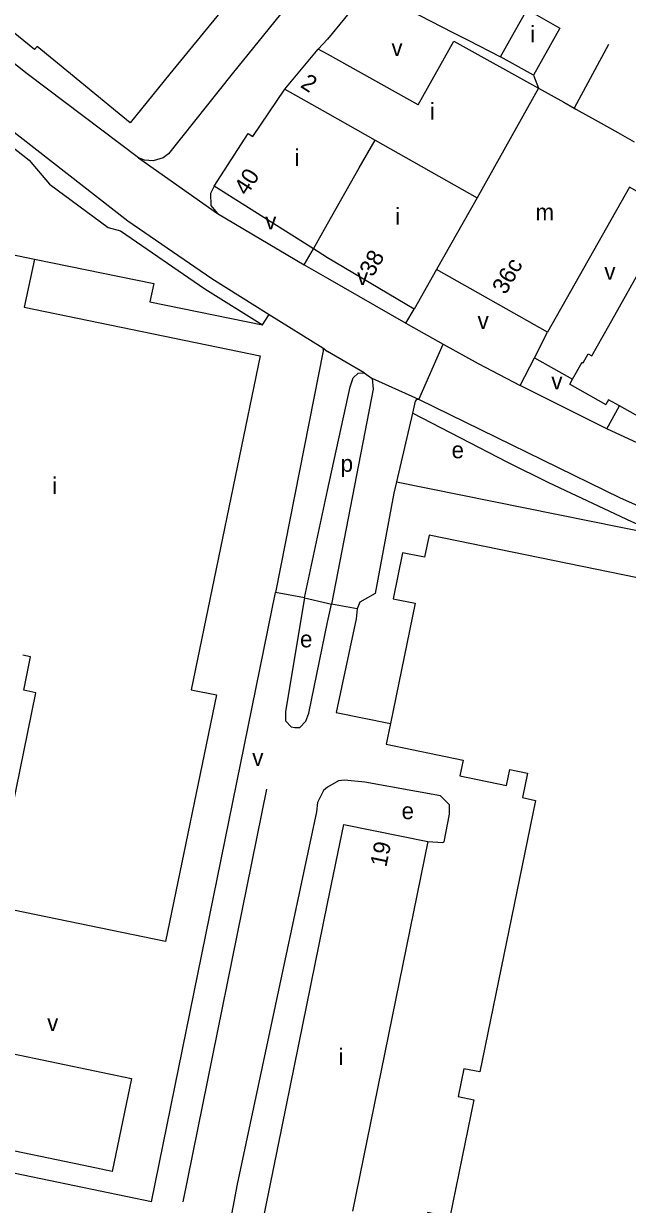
# Model space of a CAD drawing. Extents: x 157699 to 159683, y 381451 to 383293.
# Drawn here: x 157977.1 to 158121.9, y 382628.7 to 382912.1 of the extents above; entities that cross this region are included whole.
import ezdxf

# ---------------------------------------------------------------- set-up
doc = ezdxf.new("R2010")
doc.units = 0
for name, color, linetype in [('BLT_Basislijn', 7, 'Continuous'), ('BLT_Bebouwing', 7, 'Continuous'), ('BLT_Centroide', 7, 'Continuous'), ('BLT_Huisnummer', 7, 'Continuous'), ('BLT_Onderverdeling_panden', 7, 'Continuous'), ('BLT_Vlakafsluiter', 7, 'Continuous')]:
    doc.layers.add(name, color=color, linetype=linetype)

msp = doc.modelspace()

# ---------------------------------------------------------------- linework, layer by layer
at = {"layer": 'BLT_Basislijn'}
for p, q in [((158059.8, 382920.44), (158050, 382908.32)), ((158066.82, 382916.77), (158080.06, 382909.99)), ((158080.06, 382909.99), (158083.69, 382908.13)), ((158050, 382908.32), (158047.72, 382905.99)), ((158083.69, 382908.13), (158091.51, 382904.12)), ((158117.37, 382907.04), (158109.18, 382891.8)), ((158099.38, 382899.71), (158100.62, 382896.62)), ((158044.37, 382854.22), (158046.57, 382858.04)), ((158050, 382850.96), (158068.74, 382840.16)), ((158034.36, 382839.78), (158036, 382842.3)), ((158068.74, 382840.16), (158070.72, 382843.57)), ((158099.6, 382831.9), (158102.78, 382838.01)), ((158096.16, 382825.26), (158099.6, 382831.9)), ((158099.6, 382831.9), (158108.75, 382826.73)), ((158117.02, 382814.81), (158120.03, 382820.33)), ((158066.51, 382802.08), (158130.82, 382789.08)), ((158044.42, 382774.3), (158050, 382800.01)), ((158007.7, 382629.31), (158037.46, 382775.55)), ((158044.42, 382774.3), (158037.46, 382775.55)), ((158044.42, 382774.3), (158050, 382773)), ((158050, 382773), (158050.9, 382772.79)), ((158050, 382768.47), (158050.9, 382772.79)), ((158057.07, 382771.66), (158050.9, 382772.79)), ((158015.3, 382629.33), (158035.45, 382728.36)), ((158007.7, 382629.31), (157932.45, 382644.98))]:
    msp.add_line(p, q, dxfattribs=at)
for points in [[(158004.65, 382879.91), (157977.9, 382900), (157966.26, 382909.27), (157938.29, 382933.57)], [(158050, 382928.32), (158027.13, 382900), (158011.79, 382880.82), (158010.52, 382879.91), (158008.17, 382879.17), (158006.02, 382879.33), (158004.65, 382879.91)], [(157968.91, 382890.58), (158002.05, 382864.75), (158022.19, 382850.94), (158036, 382842.3)], [(157968.49, 382887.1), (157978.42, 382879.32), (157983.26, 382873.56), (157997.33, 382863.18), (158000.28, 382862.32), (158020.55, 382848.43), (158034.36, 382839.78)], [(158022.79, 382873.09), (158021.87, 382871.35), (158021.96, 382868.41), (158023.59, 382866.52)], [(158023.59, 382866.52), (158044.37, 382854.22)], [(157979.64, 382855.59), (158008.27, 382849.74), (158007.36, 382845.29), (158034.36, 382839.78)], [(158044.37, 382854.22), (158050, 382850.96)], [(158036, 382842.3), (158048.82, 382834.27)], [(158068.74, 382840.16), (158069.29, 382839.84), (158077.69, 382835.16)], [(158048.82, 382834.27), (158048.91, 382833.52), (158046.65, 382822.2), (158037.46, 382775.55)], [(158077.69, 382835.16), (158086.1, 382830.48), (158096.16, 382825.26)], [(158050, 382800.01), (158055.41, 382824.95), (158056.13, 382827.06), (158057.31, 382828.17), (158058.77, 382828.26)], [(158060.68, 382826.92), (158060.91, 382824.35), (158050.9, 382772.79)], [(158058.77, 382828.26), (158060.68, 382826.92)], [(158117.02, 382814.81), (158096.16, 382825.26)], [(158071.88, 382821.87), (158071.31, 382821.89), (158070.99, 382821.49), (158070.33, 382818.61)], [(158207.29, 382764.61), (158187.44, 382770.88), (158147.52, 382786.08), (158120.25, 382798.17), (158071.88, 382821.87)], [(158070.33, 382818.61), (158066.51, 382802.08)], [(158130.82, 382789.08), (158122.95, 382792.52), (158103.06, 382801.86), (158093.21, 382806.75), (158070.33, 382818.61)], [(158138.07, 382805.1), (158117.02, 382814.81)], [(158066.51, 382802.08), (158065.89, 382799.39)], [(158065.89, 382799.39), (158061.38, 382775.35), (158057.73, 382773.22), (158057.07, 382771.66)], [(158044.42, 382774.3), (158039.9, 382747.03), (158039.9, 382744.74), (158041.24, 382743.28), (158042.13, 382743.12), (158043.34, 382743.17), (158044.78, 382744.68), (158045.47, 382746.62), (158050, 382768.47)], [(158057.07, 382771.66), (158056.82, 382769.24)], [(158056.82, 382769.24), (158053.29, 382752.79), (158052.07, 382746.79), (158065.05, 382744.09)], [(158050, 382728.84), (158049.04, 382728.04), (158047.57, 382725.13), (158047.35, 382722.9), (158028.29, 382633.59), (158023.36, 382607.28), (158023.67, 382605.44), (158024.49, 382603.94), (158026.38, 382601.73), (158027.5, 382601.2), (158050, 382596.73)], [(158074.01, 382715.81), (158077.66, 382715.56), (158077.98, 382715.72), (158079.24, 382722.34), (158079.2, 382724.6), (158077.07, 382726.72), (158058.9, 382730.02), (158054.07, 382730.49), (158052.57, 382730.38), (158050, 382728.84)]]:
    msp.add_lwpolyline(points, dxfattribs=at)
at = {"layer": 'BLT_Bebouwing'}
for p, q in [((158091.51, 382904.12), (158094.87, 382910.08)), ((158050, 382904.74), (158047.72, 382905.99)), ((158106.64, 382893.23), (158109.18, 382891.8)), ((158109.18, 382891.8), (158109.55, 382891.59)), ((158109.55, 382891.59), (158114.9, 382888.57)), ((158114.9, 382888.57), (158119.59, 382885.92)), ((158119.59, 382885.92), (158123.51, 382883.71)), ((158046.57, 382858.04), (158022.79, 382873.09)), ((158122.44, 382872.85), (158102.78, 382838.01)), ((158050, 382855.86), (158046.57, 382858.04)), ((158070.72, 382843.57), (158050, 382855.86)), ((158076.13, 382853.04), (158070.72, 382843.57)), ((158102.78, 382838.01), (158076.13, 382853.04)), ((158108.09, 382825.56), (158108.75, 382826.73)), ((158108.09, 382825.56), (158116.78, 382820.67)), ((158140.4, 382808.83), (158120.03, 382820.33)), ((158074.01, 382715.81), (158055.97, 382627.04)), ((157945.23, 382670.92), (158002.95, 382658.94))]:
    msp.add_line(p, q, dxfattribs=at)
for points in [[(157980.27, 382906.59), (157979.68, 382905.87), (157964.22, 382918.47), (157977.09, 382934.26), (157974.11, 382936.69), (157978.79, 382942.44), (157981.77, 382940), (157982.5, 382940.9)], [(158028.13, 382919.64), (158012.17, 382900), (158002.62, 382888.25), (158000, 382890.4), (157988.3, 382900), (157980.27, 382906.59)], [(158094.87, 382910.08), (158097.9, 382915.45), (158105.74, 382911.03)], [(158105.74, 382911.03), (158099.38, 382899.71)], [(158071.71, 382892.56), (158080.3, 382907.85), (158100.62, 382896.62)], [(158039.74, 382896.36), (158047.72, 382905.99)], [(158071.71, 382892.56), (158050, 382904.74)], [(158099.38, 382899.71), (158091.51, 382904.12)], [(158022.79, 382873.09), (158030.91, 382885.71), (158032.09, 382884.96), (158039.74, 382896.36)], [(158100.62, 382896.62), (158106.64, 382893.23)], [(158117.43, 382839.55), (158132.86, 382866.89), (158122.44, 382872.85)], [(157948.3, 382840.19), (157950.14, 382849.17), (157941.39, 382850.97), (157943.37, 382860.61), (157961.04, 382856.97), (157961.51, 382859.29), (157979.64, 382855.59)], [(157979.64, 382855.59), (157977.22, 382844.04)], [(157977.22, 382844.04), (158033.83, 382832.37), (158017.25, 382752.19), (158023.35, 382751.03), (158011.13, 382691.79)], [(158108.75, 382826.73), (158111.06, 382830.85), (158111.3, 382830.71), (158112.5, 382832.83), (158113.36, 382832.34), (158117.43, 382839.55)], [(158120.03, 382820.33), (158117.42, 382821.8), (158116.78, 382820.67)], [(158171.64, 382747.4), (158173.82, 382757.93), (158141.98, 382764.41), (158144.22, 382774.98), (158074.33, 382789.35), (158073.25, 382784), (158068, 382785.1), (158065.73, 382774.05), (158070.97, 382772.97), (158065.05, 382744.09)], [(158011.13, 382691.79), (157969.49, 382700.36), (157980.02, 382751.51), (157977.09, 382752.11), (157978.74, 382760.14), (157976.89, 382760.52)], [(158065.05, 382744.09), (158064.03, 382739.16), (158082.51, 382735.35), (158081.7, 382731.53), (158092.94, 382729.21), (158093.74, 382733.06), (158097.94, 382732.2), (158096.75, 382726.32), (158099.84, 382725.66), (158086.48, 382660.51), (158082.67, 382661.26), (158081.31, 382654.6), (158085.1, 382653.82), (158079.31, 382625.67), (158073.93, 382626.78), (158068.95, 382602.56), (158117.29, 382592.52), (158109.76, 382555.86)], [(158050, 382700.92), (158053.86, 382719.91), (158074.01, 382715.81)], [(158050, 382604.65), (158039.95, 382606.69), (158039.43, 382604.18), (158033.02, 382605.5), (158033.54, 382607.99), (158031.21, 382608.47), (158050, 382700.92)], [(158002.95, 382658.94), (157998.32, 382636.62), (157993.05, 382637.71)], [(157993.05, 382637.71), (157940.6, 382648.6)]]:
    msp.add_lwpolyline(points, dxfattribs=at)
at = {"layer": 'BLT_Onderverdeling_panden'}
for p, q in [((158039.74, 382896.36), (158050, 382890.56)), ((158050, 382864.05), (158057.6, 382877.45)), ((158046.57, 382858.04), (158050, 382864.05))]:
    msp.add_line(p, q, dxfattribs=at)
for points in [[(158100.62, 382896.62), (158085.86, 382870.3)], [(158050, 382890.56), (158061.38, 382884.13)], [(158057.6, 382877.45), (158061.38, 382884.13)], [(158061.38, 382884.13), (158085.86, 382870.3)], [(158085.86, 382870.3), (158076.13, 382853.04)]]:
    msp.add_lwpolyline(points, dxfattribs=at)
at = {"layer": 'BLT_Vlakafsluiter'}
for p, q in [((158004.65, 382879.91), (158023.59, 382866.52)), ((158048.82, 382834.27), (158050, 382833.4)), ((158058.77, 382828.26), (158050, 382833.4)), ((158071.88, 382821.87), (158077.69, 382835.16)), ((158071.88, 382821.87), (158060.68, 382826.92))]:
    msp.add_line(p, q, dxfattribs=at)

# ---------------------------------------------------------------- texts
at = {"layer": 'BLT_Centroide'}
for s, p in [('i', (158098.62, 382907.58)), ('v', (158065.31, 382904.32)), ('i', (158074.51, 382889.06)), ('i', (158042.08, 382877.95)), ('i', (158066.22, 382863.83)), ('m', (158099.87, 382864.84)), ('v', (158035.02, 382862.7)), ('v', (158057.06, 382849.35)), ('v', (158116.39, 382850.61)), ('v', (158085.98, 382838.81)), ('v', (158103.67, 382824.29)), ('e', (158079.74, 382807.77)), ('p', (158053.12, 382804.52)), ('i', (157983.89, 382799.19)), ('e', (158043.38, 382762.39)), ('v', (158031.92, 382733.94)), ('e', (158067.74, 382721.16)), ('v', (157982.71, 382670.32)), ('i', (158052.61, 382662.14))]:
    msp.add_text(s, height=4, dxfattribs=at).set_placement(p)
at = {"layer": 'BLT_Huisnummer'}
for s, rotation, p in [('2', 327.2207, (158043.25, 382896.97)), ('40', 57.6741, (158030.64, 382870.61)), ('38', 60.2564, (158060.83, 382851.09)), ('36c', 60.565, (158092.7, 382846.84)), ('19', 78.2702, (158064.06, 382709.49))]:
    msp.add_text(s, height=4, rotation=rotation, dxfattribs=at).set_placement(p)

doc.saveas('drawing.dxf')
